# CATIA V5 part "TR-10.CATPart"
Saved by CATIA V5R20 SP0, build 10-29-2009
Part number: _TR-10
Definition: NONE
Nomenclature: _TR-10
Source: Unknown
Description: PART-_TR-10-DESC
Bounding box of the stored display mesh (mm): x 0 to 12.5, y -5.9 to 5.9, z -5.9 to 5.9
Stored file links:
  C:\Users\Utente\Desktop\IO LAVORO\3D X SITO CF\X SITO\PLASTICA\TR\TR-10.CATPart
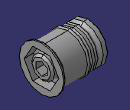
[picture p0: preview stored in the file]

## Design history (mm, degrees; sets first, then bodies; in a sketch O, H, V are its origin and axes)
Body1 "_TR-10" (main body)
  Solid1: solid without history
